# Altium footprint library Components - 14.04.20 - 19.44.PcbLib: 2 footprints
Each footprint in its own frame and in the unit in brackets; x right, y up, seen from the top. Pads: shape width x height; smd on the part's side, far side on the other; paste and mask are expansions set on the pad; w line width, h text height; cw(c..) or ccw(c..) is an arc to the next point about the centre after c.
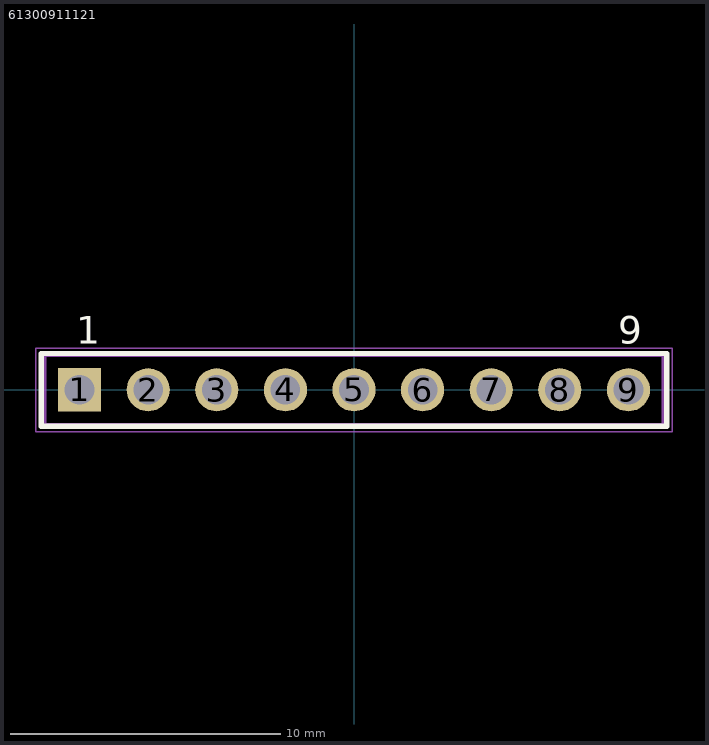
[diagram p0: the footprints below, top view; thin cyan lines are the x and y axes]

## 61300911121 [mm] "Pin Header, pitch 2.54 mm, THT, Vertical, single row, 9p"
height 8.54
pads (9):
  rect 1.6x1.6 hole 1.1: 1(-10.16,0)
  round 1.6 hole 1.1: 2(-7.62,0) 3(-5.08,0) 4(-2.54,0) 5(0,0) 6(2.54,0) 7(5.08,0) 8(7.62,0) 9(10.16,0)
Top Overlay:
  lines w0.2: -11.58,-1.345 -11.58,1.345 11.58,1.345 11.58,-1.345 -11.58,-1.345
  text "9" at 9.78,1.7 h1.02
  text "1" at -10.28,1.7 h1.02
Mechanical 13:
  lines w0.1: -11.43,-1.27 11.43,-1.27 11.43,1.27 -11.43,1.27 -11.43,-1.27
Mechanical 15:
  lines w0.05: -0.5,0 0.5,0 ; 0,-0.5 0,0.5 ; -11.78,-1.545 11.78,-1.545 11.78,1.545 -11.78,1.545 -11.78,-1.545
3D body "61300911121.stp": height 8.57, standoff -2.97, extent -11.43,-1.27 11.43,1.27

## PCBComponent_1 [mm]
